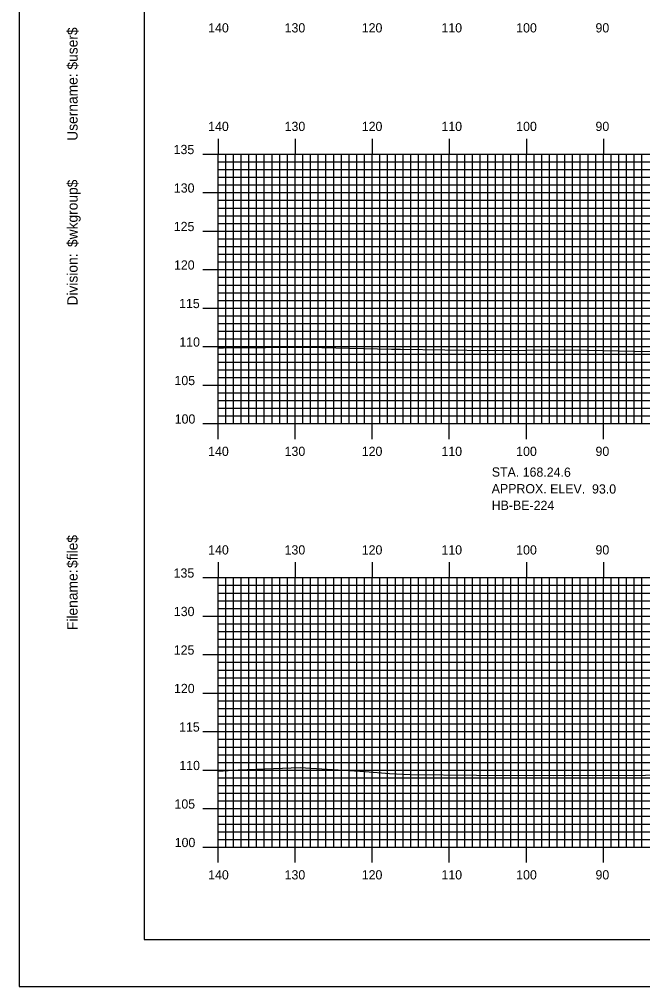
# Model space of a CAD drawing. Extents: x 1781860 to 1782203, y 442591 to 442811.
# Drawn here: x 1781860.1 to 1781941, y 442590.5 to 442716.2 of the extents above; entities that cross this region are included whole.
import ezdxf

# ---------------------------------------------------------------- set-up
doc = ezdxf.new("R2010")
doc.units = 0
for name, color, linetype in [('BORDER', 7, 'Continuous'), ('BORING - REFUSAL', 7, 'Continuous'), ('H_V ANNOTATION', 7, 'Continuous'), ('MAJOR', 7, 'Continuous'), ('MINOR', 7, 'Continuous'), ('PLOT BOUNDARY', 7, 'Continuous'), ('S_Roadway_Centerline', 7, 'Continuous')]:
    doc.layers.add(name, color=color, linetype=linetype)

msp = doc.modelspace()

# ---------------------------------------------------------------- linework, layer by layer
at = {"layer": 'BORDER'}
msp.add_lwpolyline([(1781876.32, 442596.67), (1782196.32, 442596.67), (1782196.32, 442806.67), (1781876.32, 442806.67)], close=True, dxfattribs=at)
at = {"layer": 'MAJOR'}
for p, q in [((1781885.92, 442700.67), (1781885.92, 442698.67)), ((1781895.92, 442700.67), (1781895.92, 442698.67)), ((1781905.92, 442700.67), (1781905.92, 442698.67)), ((1781915.92, 442700.67), (1781915.92, 442698.67)), ((1781925.92, 442700.67), (1781925.92, 442698.67)), ((1781935.92, 442700.67), (1781935.92, 442698.67)), ((1781883.92, 442698.67), (1781885.92, 442698.67)), ((1781885.92, 442698.67), (1782165.92, 442698.67)), ((1781885.92, 442663.67), (1781885.92, 442698.67)), ((1781885.92, 442663.67), (1781885.92, 442698.67)), ((1781885.92, 442698.67), (1782165.92, 442698.67)), ((1781895.92, 442663.67), (1781895.92, 442698.67)), ((1781905.92, 442663.67), (1781905.92, 442698.67)), ((1781915.92, 442663.67), (1781915.92, 442698.67)), ((1781925.92, 442663.67), (1781925.92, 442698.67)), ((1781935.92, 442663.67), (1781935.92, 442698.67)), ((1781883.92, 442693.67), (1781885.92, 442693.67)), ((1781885.92, 442693.67), (1782165.92, 442693.67)), ((1781883.92, 442688.67), (1781885.92, 442688.67)), ((1781885.92, 442688.67), (1782165.92, 442688.67)), ((1781883.92, 442683.67), (1781885.92, 442683.67)), ((1781885.92, 442683.67), (1782165.92, 442683.67)), ((1781883.92, 442678.67), (1781885.92, 442678.67)), ((1781885.92, 442678.67), (1782165.92, 442678.67)), ((1781883.92, 442673.67), (1781885.92, 442673.67)), ((1781885.92, 442673.67), (1782165.92, 442673.67)), ((1781883.92, 442668.67), (1781885.92, 442668.67)), ((1781885.92, 442668.67), (1782165.92, 442668.67)), ((1781883.92, 442663.67), (1781885.92, 442663.67)), ((1781885.92, 442663.67), (1782165.92, 442663.67)), ((1781885.92, 442663.67), (1782165.92, 442663.67)), ((1781885.92, 442661.66), (1781885.92, 442663.67)), ((1781895.92, 442661.66), (1781895.92, 442663.67)), ((1781905.92, 442661.66), (1781905.92, 442663.67)), ((1781915.92, 442661.66), (1781915.92, 442663.67)), ((1781925.92, 442661.66), (1781925.92, 442663.67)), ((1781935.92, 442661.66), (1781935.92, 442663.67)), ((1781885.92, 442645.67), (1781885.92, 442643.67)), ((1781895.92, 442645.67), (1781895.92, 442643.67)), ((1781905.92, 442645.67), (1781905.92, 442643.67)), ((1781915.92, 442645.67), (1781915.92, 442643.67)), ((1781925.92, 442645.67), (1781925.92, 442643.67)), ((1781935.92, 442645.67), (1781935.92, 442643.67)), ((1781883.92, 442643.67), (1781885.92, 442643.67)), ((1781885.92, 442643.67), (1782165.92, 442643.67)), ((1781885.92, 442608.67), (1781885.92, 442643.67)), ((1781885.92, 442608.67), (1781885.92, 442643.67)), ((1781885.92, 442643.67), (1782165.92, 442643.67)), ((1781895.92, 442608.67), (1781895.92, 442643.67)), ((1781905.92, 442608.67), (1781905.92, 442643.67)), ((1781915.92, 442608.67), (1781915.92, 442643.67)), ((1781925.92, 442608.67), (1781925.92, 442643.67)), ((1781935.92, 442608.67), (1781935.92, 442643.67)), ((1781883.92, 442638.67), (1781885.92, 442638.67)), ((1781885.92, 442638.67), (1782165.92, 442638.67)), ((1781883.92, 442633.67), (1781885.92, 442633.67)), ((1781885.92, 442633.67), (1782165.92, 442633.67)), ((1781883.92, 442628.67), (1781885.92, 442628.67)), ((1781885.92, 442628.67), (1782165.92, 442628.67)), ((1781883.92, 442623.67), (1781885.92, 442623.67)), ((1781885.92, 442623.67), (1782165.92, 442623.67)), ((1781883.92, 442618.67), (1781885.92, 442618.67)), ((1781885.92, 442618.67), (1782165.92, 442618.67)), ((1781883.92, 442613.67), (1781885.92, 442613.67)), ((1781885.92, 442613.67), (1782165.92, 442613.67)), ((1781883.92, 442608.67), (1781885.92, 442608.67)), ((1781885.92, 442608.67), (1782165.92, 442608.67)), ((1781885.92, 442608.67), (1782165.92, 442608.67)), ((1781885.92, 442606.66), (1781885.92, 442608.67)), ((1781895.92, 442606.66), (1781895.92, 442608.67)), ((1781905.92, 442606.66), (1781905.92, 442608.67)), ((1781915.92, 442606.66), (1781915.92, 442608.67)), ((1781925.92, 442606.66), (1781925.92, 442608.67)), ((1781935.92, 442606.66), (1781935.92, 442608.67))]:
    msp.add_line(p, q, dxfattribs=at)
at = {"layer": 'MINOR'}
for p, q in [((1781886.92, 442663.67), (1781886.92, 442698.67)), ((1781887.92, 442663.67), (1781887.92, 442698.67)), ((1781888.92, 442663.67), (1781888.92, 442698.67)), ((1781889.92, 442663.67), (1781889.92, 442698.67)), ((1781890.92, 442663.67), (1781890.92, 442698.67)), ((1781891.92, 442663.67), (1781891.92, 442698.67)), ((1781892.92, 442663.67), (1781892.92, 442698.67)), ((1781893.92, 442663.67), (1781893.92, 442698.67)), ((1781894.92, 442663.67), (1781894.92, 442698.67)), ((1781896.92, 442663.67), (1781896.92, 442698.67)), ((1781897.92, 442663.67), (1781897.92, 442698.67)), ((1781898.92, 442663.67), (1781898.92, 442698.67)), ((1781899.92, 442663.67), (1781899.92, 442698.67)), ((1781900.92, 442663.67), (1781900.92, 442698.67)), ((1781901.92, 442663.67), (1781901.92, 442698.67)), ((1781902.92, 442663.67), (1781902.92, 442698.67)), ((1781903.92, 442663.67), (1781903.92, 442698.67)), ((1781904.92, 442663.67), (1781904.92, 442698.67)), ((1781906.92, 442663.67), (1781906.92, 442698.67)), ((1781907.92, 442663.67), (1781907.92, 442698.67)), ((1781908.92, 442663.67), (1781908.92, 442698.67)), ((1781909.92, 442663.67), (1781909.92, 442698.67)), ((1781910.92, 442663.67), (1781910.92, 442698.67)), ((1781911.92, 442663.67), (1781911.92, 442698.67)), ((1781912.92, 442663.67), (1781912.92, 442698.67)), ((1781913.92, 442663.67), (1781913.92, 442698.67)), ((1781914.92, 442663.67), (1781914.92, 442698.67)), ((1781916.92, 442663.67), (1781916.92, 442698.67)), ((1781917.92, 442663.67), (1781917.92, 442698.67)), ((1781918.92, 442663.67), (1781918.92, 442698.67)), ((1781919.92, 442663.67), (1781919.92, 442698.67)), ((1781920.92, 442663.67), (1781920.92, 442698.67)), ((1781921.92, 442663.67), (1781921.92, 442698.67)), ((1781922.92, 442663.67), (1781922.92, 442698.67)), ((1781923.92, 442663.67), (1781923.92, 442698.67)), ((1781924.92, 442663.67), (1781924.92, 442698.67)), ((1781926.92, 442663.67), (1781926.92, 442698.67)), ((1781927.92, 442663.67), (1781927.92, 442698.67)), ((1781928.92, 442663.67), (1781928.92, 442698.67)), ((1781929.92, 442663.67), (1781929.92, 442698.67)), ((1781930.92, 442663.67), (1781930.92, 442698.67)), ((1781931.92, 442663.67), (1781931.92, 442698.67)), ((1781932.92, 442663.67), (1781932.92, 442698.67)), ((1781933.92, 442663.67), (1781933.92, 442698.67)), ((1781934.92, 442663.67), (1781934.92, 442698.67)), ((1781936.92, 442663.67), (1781936.92, 442698.67)), ((1781937.92, 442663.67), (1781937.92, 442698.67)), ((1781938.92, 442663.67), (1781938.92, 442698.67)), ((1781939.92, 442663.67), (1781939.92, 442698.67)), ((1781940.92, 442663.67), (1781940.92, 442698.67)), ((1781885.92, 442697.67), (1782165.92, 442697.67)), ((1781885.92, 442697.67), (1781887.92, 442697.67)), ((1781885.92, 442696.67), (1782165.92, 442696.67)), ((1781885.92, 442696.67), (1781887.92, 442696.67)), ((1781885.92, 442695.67), (1782165.92, 442695.67)), ((1781885.92, 442695.67), (1781887.92, 442695.67)), ((1781885.92, 442694.67), (1782165.92, 442694.67)), ((1781885.92, 442694.67), (1781887.92, 442694.67)), ((1781885.92, 442692.67), (1782165.92, 442692.67)), ((1781885.92, 442692.67), (1781887.92, 442692.67)), ((1781885.92, 442691.67), (1782165.92, 442691.67)), ((1781885.92, 442691.67), (1781887.92, 442691.67)), ((1781885.92, 442690.67), (1782165.92, 442690.67)), ((1781885.92, 442690.67), (1781887.92, 442690.67)), ((1781885.92, 442689.67), (1782165.92, 442689.67)), ((1781885.92, 442689.67), (1781887.92, 442689.67)), ((1781885.92, 442687.67), (1782165.92, 442687.67)), ((1781885.92, 442687.67), (1781887.92, 442687.67)), ((1781885.92, 442686.67), (1782165.92, 442686.67)), ((1781885.92, 442686.67), (1781887.92, 442686.67)), ((1781885.92, 442685.67), (1782165.92, 442685.67)), ((1781885.92, 442685.67), (1781887.92, 442685.67)), ((1781885.92, 442684.67), (1782165.92, 442684.67)), ((1781885.92, 442684.67), (1781887.92, 442684.67)), ((1781885.92, 442682.67), (1782165.92, 442682.67)), ((1781885.92, 442682.67), (1781887.92, 442682.67)), ((1781885.92, 442681.67), (1782165.92, 442681.67)), ((1781885.92, 442681.67), (1781887.92, 442681.67)), ((1781885.92, 442680.67), (1782165.92, 442680.67)), ((1781885.92, 442680.67), (1781887.92, 442680.67)), ((1781885.92, 442679.67), (1782165.92, 442679.67)), ((1781885.92, 442679.67), (1781887.92, 442679.67)), ((1781885.92, 442677.67), (1782165.92, 442677.67)), ((1781885.92, 442677.67), (1781887.92, 442677.67)), ((1781885.92, 442676.67), (1782165.92, 442676.67)), ((1781885.92, 442676.67), (1781887.92, 442676.67)), ((1781885.92, 442675.67), (1782165.92, 442675.67)), ((1781885.92, 442675.67), (1781887.92, 442675.67)), ((1781885.92, 442674.67), (1782165.92, 442674.67)), ((1781885.92, 442674.67), (1781887.92, 442674.67)), ((1781885.92, 442672.67), (1782165.92, 442672.67)), ((1781885.92, 442672.67), (1781887.92, 442672.67)), ((1781885.92, 442671.67), (1782165.92, 442671.67)), ((1781885.92, 442671.67), (1781887.92, 442671.67)), ((1781885.92, 442670.67), (1782165.92, 442670.67)), ((1781885.92, 442670.67), (1781887.92, 442670.67)), ((1781885.92, 442669.67), (1782165.92, 442669.67)), ((1781885.92, 442669.67), (1781887.92, 442669.67)), ((1781885.92, 442667.67), (1782165.92, 442667.67)), ((1781885.92, 442667.67), (1781887.92, 442667.67)), ((1781885.92, 442666.67), (1782165.92, 442666.67)), ((1781885.92, 442666.67), (1781887.92, 442666.67)), ((1781885.92, 442665.67), (1782165.92, 442665.67)), ((1781885.92, 442665.67), (1781887.92, 442665.67)), ((1781885.92, 442664.67), (1782165.92, 442664.67)), ((1781885.92, 442664.67), (1781887.92, 442664.67)), ((1781886.92, 442608.67), (1781886.92, 442643.67)), ((1781887.92, 442608.67), (1781887.92, 442643.67)), ((1781888.92, 442608.67), (1781888.92, 442643.67)), ((1781889.92, 442608.67), (1781889.92, 442643.67)), ((1781890.92, 442608.67), (1781890.92, 442643.67)), ((1781891.92, 442608.67), (1781891.92, 442643.67)), ((1781892.92, 442608.67), (1781892.92, 442643.67)), ((1781893.92, 442608.67), (1781893.92, 442643.67)), ((1781894.92, 442608.67), (1781894.92, 442643.67)), ((1781896.92, 442608.67), (1781896.92, 442643.67)), ((1781897.92, 442608.67), (1781897.92, 442643.67)), ((1781898.92, 442608.67), (1781898.92, 442643.67)), ((1781899.92, 442608.67), (1781899.92, 442643.67)), ((1781900.92, 442608.67), (1781900.92, 442643.67)), ((1781901.92, 442608.67), (1781901.92, 442643.67)), ((1781902.92, 442608.67), (1781902.92, 442643.67)), ((1781903.92, 442608.67), (1781903.92, 442643.67)), ((1781904.92, 442608.67), (1781904.92, 442643.67)), ((1781906.92, 442608.67), (1781906.92, 442643.67)), ((1781907.92, 442608.67), (1781907.92, 442643.67)), ((1781908.92, 442608.67), (1781908.92, 442643.67)), ((1781909.92, 442608.67), (1781909.92, 442643.67)), ((1781910.92, 442608.67), (1781910.92, 442643.67)), ((1781911.92, 442608.67), (1781911.92, 442643.67)), ((1781912.92, 442608.67), (1781912.92, 442643.67)), ((1781913.92, 442608.67), (1781913.92, 442643.67)), ((1781914.92, 442608.67), (1781914.92, 442643.67)), ((1781916.92, 442608.67), (1781916.92, 442643.67)), ((1781917.92, 442608.67), (1781917.92, 442643.67)), ((1781918.92, 442608.67), (1781918.92, 442643.67)), ((1781919.92, 442608.67), (1781919.92, 442643.67)), ((1781920.92, 442608.67), (1781920.92, 442643.67)), ((1781921.92, 442608.67), (1781921.92, 442643.67)), ((1781922.92, 442608.67), (1781922.92, 442643.67)), ((1781923.92, 442608.67), (1781923.92, 442643.67)), ((1781924.92, 442608.67), (1781924.92, 442643.67)), ((1781926.92, 442608.67), (1781926.92, 442643.67)), ((1781927.92, 442608.67), (1781927.92, 442643.67)), ((1781928.92, 442608.67), (1781928.92, 442643.67)), ((1781929.92, 442608.67), (1781929.92, 442643.67)), ((1781930.92, 442608.67), (1781930.92, 442643.67)), ((1781931.92, 442608.67), (1781931.92, 442643.67)), ((1781932.92, 442608.67), (1781932.92, 442643.67)), ((1781933.92, 442608.67), (1781933.92, 442643.67)), ((1781934.92, 442608.67), (1781934.92, 442643.67)), ((1781936.92, 442608.67), (1781936.92, 442643.67)), ((1781937.92, 442608.67), (1781937.92, 442643.67)), ((1781938.92, 442608.67), (1781938.92, 442643.67)), ((1781939.92, 442608.67), (1781939.92, 442643.67)), ((1781940.92, 442608.67), (1781940.92, 442643.67)), ((1781885.92, 442642.67), (1782165.92, 442642.67)), ((1781885.92, 442642.67), (1781887.92, 442642.67)), ((1781885.92, 442641.67), (1782165.92, 442641.67)), ((1781885.92, 442641.67), (1781887.92, 442641.67)), ((1781885.92, 442640.67), (1782165.92, 442640.67)), ((1781885.92, 442640.67), (1781887.92, 442640.67)), ((1781885.92, 442639.67), (1782165.92, 442639.67)), ((1781885.92, 442639.67), (1781887.92, 442639.67)), ((1781885.92, 442637.67), (1782165.92, 442637.67)), ((1781885.92, 442637.67), (1781887.92, 442637.67)), ((1781885.92, 442636.67), (1782165.92, 442636.67)), ((1781885.92, 442636.67), (1781887.92, 442636.67)), ((1781885.92, 442635.67), (1782165.92, 442635.67)), ((1781885.92, 442635.67), (1781887.92, 442635.67)), ((1781885.92, 442634.67), (1782165.92, 442634.67)), ((1781885.92, 442634.67), (1781887.92, 442634.67)), ((1781885.92, 442632.67), (1782165.92, 442632.67)), ((1781885.92, 442632.67), (1781887.92, 442632.67)), ((1781885.92, 442631.67), (1782165.92, 442631.67)), ((1781885.92, 442631.67), (1781887.92, 442631.67)), ((1781885.92, 442630.67), (1782165.92, 442630.67)), ((1781885.92, 442630.67), (1781887.92, 442630.67)), ((1781885.92, 442629.67), (1782165.92, 442629.67)), ((1781885.92, 442629.67), (1781887.92, 442629.67)), ((1781885.92, 442627.67), (1782165.92, 442627.67)), ((1781885.92, 442627.67), (1781887.92, 442627.67)), ((1781885.92, 442626.67), (1782165.92, 442626.67)), ((1781885.92, 442626.67), (1781887.92, 442626.67)), ((1781885.92, 442625.67), (1782165.92, 442625.67)), ((1781885.92, 442625.67), (1781887.92, 442625.67)), ((1781885.92, 442624.67), (1782165.92, 442624.67)), ((1781885.92, 442624.67), (1781887.92, 442624.67)), ((1781885.92, 442622.67), (1782165.92, 442622.67)), ((1781885.92, 442622.67), (1781887.92, 442622.67)), ((1781885.92, 442621.67), (1782165.92, 442621.67)), ((1781885.92, 442621.67), (1781887.92, 442621.67)), ((1781885.92, 442620.67), (1782165.92, 442620.67)), ((1781885.92, 442620.67), (1781887.92, 442620.67)), ((1781885.92, 442619.67), (1782165.92, 442619.67)), ((1781885.92, 442619.67), (1781887.92, 442619.67)), ((1781885.92, 442617.67), (1782165.92, 442617.67)), ((1781885.92, 442617.67), (1781887.92, 442617.67)), ((1781885.92, 442616.67), (1782165.92, 442616.67)), ((1781885.92, 442616.67), (1781887.92, 442616.67)), ((1781885.92, 442615.67), (1782165.92, 442615.67)), ((1781885.92, 442615.67), (1781887.92, 442615.67)), ((1781885.92, 442614.67), (1782165.92, 442614.67)), ((1781885.92, 442614.67), (1781887.92, 442614.67)), ((1781885.92, 442612.67), (1782165.92, 442612.67)), ((1781885.92, 442612.67), (1781887.92, 442612.67)), ((1781885.92, 442611.67), (1782165.92, 442611.67)), ((1781885.92, 442611.67), (1781887.92, 442611.67)), ((1781885.92, 442610.67), (1782165.92, 442610.67)), ((1781885.92, 442610.67), (1781887.92, 442610.67)), ((1781885.92, 442609.67), (1782165.92, 442609.67)), ((1781885.92, 442609.67), (1781887.92, 442609.67))]:
    msp.add_line(p, q, dxfattribs=at)
at = {"layer": 'PLOT BOUNDARY'}
msp.add_lwpolyline([(1781860.13, 442590.55), (1782200.13, 442590.55), (1782200.13, 442810.55), (1781860.13, 442810.55)], close=True, dxfattribs=at)
at = {"layer": 'S_Roadway_Centerline'}
for points in [[(1781885.92, 442673.53), (1781886.64, 442673.52), (1781897.56, 442673.61), (1781908.41, 442673.34), (1781909, 442673.33), (1781909.59, 442673.32), (1781921.1, 442673.18), (1781930.79, 442673.23), (1781933.76, 442673.2), (1781944.09, 442673.01), (1781954.67, 442673.47), (1781959.27, 442673.5), (1781977.13, 442673), (1781980.69, 442672.98), (1781990.57, 442673.26), (1782004.47, 442673.22), (1782014.46, 442673.3), (1782021.16, 442673.31), (1782025.72, 442673.25), (1782030.25, 442673.23), (1782037.34, 442673.36), (1782045, 442673.37), (1782053.31, 442673.39), (1782060.57, 442673.51)], [(1781885.92, 442618.55), (1781888.53, 442618.72), (1781896.56, 442619), (1781904.99, 442618.5), (1781908.14, 442618.21), (1781910.85, 442618.11), (1781919.43, 442618.01), (1781929.39, 442617.96), (1781931.41, 442618.01), (1781934.56, 442617.96), (1781954.99, 442618.1), (1781962.36, 442618.05), (1781966.96, 442618.03), (1781969.02, 442617.98), (1781987.63, 442617.88), (1781991.03, 442617.95), (1782010.21, 442618.07), (1782015.63, 442617.91), (1782024.85, 442617.66), (1782032.79, 442617.5), (1782040.55, 442617.47), (1782047.74, 442617.48), (1782055.57, 442617.74), (1782059.11, 442617.89)]]:
    msp.add_lwpolyline(points, dxfattribs=at)

# ---------------------------------------------------------------- texts
at = {"layer": 'BORDER'}
for s, p in [('$user$', (1781867.69, 442709.65)), ('Username:', (1781867.69, 442700.4)), ('$wkgroup$', (1781867.69, 442686.6)), ('Division:', (1781867.69, 442679)), ('$file$', (1781867.69, 442644.92)), ('Filename:', (1781867.69, 442636.86))]:
    msp.add_text(s, height=1.339, rotation=90, dxfattribs=at).set_placement(p)
at = {"layer": 'BORING - REFUSAL'}
for s, p in [('STA. 168.24.6', (1781921.43, 442656.79)), ('APPROX. ELEV.  93.0', (1781921.42, 442654.63)), ('HB-BE-224', (1781921.42, 442652.47))]:
    msp.add_text(s, height=1.2, rotation=359.8142, dxfattribs=at).set_placement(p)
at = {"layer": 'H_V ANNOTATION'}
for s, p in [('140', (1781884.63, 442714.47)), ('130', (1781894.55, 442714.47)), ('120', (1781904.56, 442714.47)), ('110', (1781914.9, 442714.47)), ('100', (1781924.6, 442714.47)), ('90', (1781934.89, 442714.47)), ('140', (1781884.63, 442701.67)), ('130', (1781894.55, 442701.67)), ('120', (1781904.56, 442701.67)), ('110', (1781914.9, 442701.67)), ('100', (1781924.6, 442701.67)), ('90', (1781934.89, 442701.67)), ('135', (1781880.15, 442698.67)), ('130', (1781880.18, 442693.67)), ('125', (1781880.17, 442688.67)), ('120', (1781880.2, 442683.67)), ('115', (1781880.86, 442678.67)), ('110', (1781880.89, 442673.67)), ('105', (1781880.26, 442668.67)), ('100', (1781880.29, 442663.67)), ('140', (1781884.63, 442659.47)), ('130', (1781894.55, 442659.47)), ('120', (1781904.56, 442659.47)), ('110', (1781914.9, 442659.47)), ('100', (1781924.6, 442659.47)), ('90', (1781934.89, 442659.47)), ('140', (1781884.63, 442646.67)), ('130', (1781894.55, 442646.67)), ('120', (1781904.56, 442646.67)), ('110', (1781914.9, 442646.67)), ('100', (1781924.6, 442646.67)), ('90', (1781934.89, 442646.67)), ('135', (1781880.15, 442643.67)), ('130', (1781880.18, 442638.67)), ('125', (1781880.17, 442633.67)), ('120', (1781880.2, 442628.67)), ('115', (1781880.86, 442623.67)), ('110', (1781880.89, 442618.67)), ('105', (1781880.26, 442613.67)), ('100', (1781880.29, 442608.67)), ('140', (1781884.63, 442604.47)), ('130', (1781894.55, 442604.47)), ('120', (1781904.56, 442604.47)), ('110', (1781914.9, 442604.47)), ('100', (1781924.6, 442604.47)), ('90', (1781934.89, 442604.47))]:
    msp.add_text(s, height=1.2, dxfattribs=at).set_placement(p)
at = {"layer": 'MAJOR'}
for p in [(1781885.91, 442663.67), (1781885.91, 442608.67)]:
    msp.add_text('-', height=0.012, dxfattribs=at).set_placement(p)

doc.saveas('drawing.dxf')
